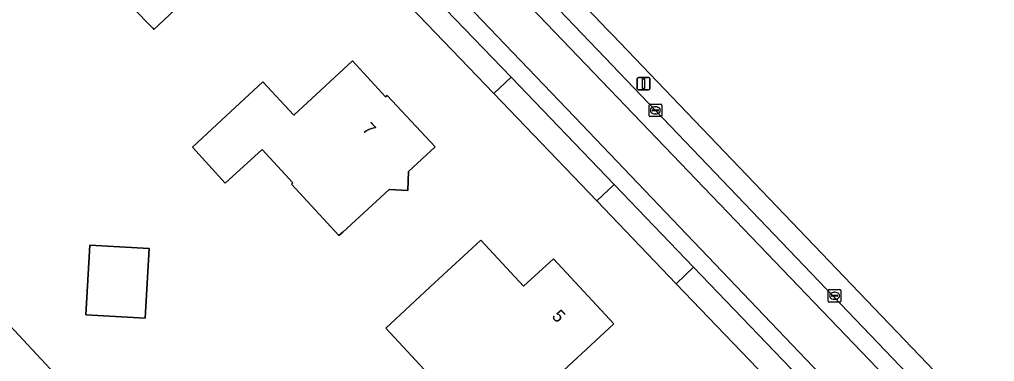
# Model space of a CAD drawing. Extents: x 156702 to 158052, y 387630 to 388992.
# Drawn here: x 157527.1 to 157604.6, y 388126 to 388153.2 of the extents above; entities that cross this region are included whole.
import ezdxf

# ---------------------------------------------------------------- set-up
doc = ezdxf.new("R2010")
doc.units = 0
for name, color, linetype in [('IMGEO_Erf', 7, 'Continuous'), ('IMGEO_Kolk', 7, 'Continuous'), ('IMGEO_Lichtmast', 7, 'Continuous'), ('IMGEO_Pand', 7, 'Continuous'), ('IMGEO_Pand_nummerreeks', 7, 'Continuous'), ('IMGEO_Pand_overbouw', 7, 'Continuous'), ('IMGEO_Rijbaan_lokaal_open', 7, 'Continuous'), ('IMGEO_Voetpad_open', 7, 'Continuous')]:
    doc.layers.add(name, color=color, linetype=linetype)

msp = doc.modelspace()

# ---------------------------------------------------------------- linework, layer by layer
at = {"layer": 'IMGEO_Erf'}
for points in [[(157587.035, 388124.121), (157579.276, 388132.213), (157572.963, 388138.799), (157564.783, 388147.336), (157558.148, 388154.267), (157555.656, 388156.858), (157540.509, 388172.666), (157529.678, 388184.162), (157518.473, 388195.859), (157513.847, 388200.675), (157504.663, 388210.298), (157501.613, 388213.475), (157500.203, 388214.779)], [(157525.186, 388203.161), (157531.652, 388196.446), (157531.904, 388196.084), (157532.708, 388195.257), (157533.058, 388194.995), (157540.381, 388187.324), (157540.603, 388187.003), (157540.852, 388186.863), (157546.974, 388180.453), (157548.872, 388178.469), (157549.792, 388177.507), (157561.008, 388165.78), (157561.677, 388165.081), (157562.03, 388164.713), (157565.006, 388161.615), (157565.368, 388161.238), (157570.562, 388155.83), (157572.789, 388153.497), (157573.82, 388152.417), (157574.214, 388152.004), (157593.208, 388132.152), (157609.438, 388115.184)]]:
    msp.add_lwpolyline(points, dxfattribs=at)
for points in [[(157546.37, 388142.894), (157543.444, 388140.22), (157540.833, 388143.085), (157542.762, 388144.87), (157546.431, 388148.265), (157548.884, 388145.629), (157553.543, 388149.959), (157556.188, 388147.085), (157556.301, 388147.194), (157560.112, 388143.094), (157558.006, 388141.139), (157557.943, 388139.618), (157556.458, 388139.708), (157552.782, 388136.32), (157552.473, 388136.036), (157548.693, 388140.141), (157548.805, 388140.243)], [(157559.128, 388124.602), (157559.582, 388125.024), (157556.195, 388128.667), (157560.077, 388132.277), (157563.738, 388135.681), (157567.141, 388132.006), (157569.518, 388134.192), (157574.323, 388129.024), (157570.657, 388125.625), (157568.76, 388123.866), (157571.405, 388121.014), (157568.776, 388118.575), (157566.131, 388121.427), (157563.948, 388119.403)], [(157532.669, 388135.275), (157537.389, 388135.006), (157537.074, 388129.477), (157532.354, 388129.747)], [(157510.363, 388087.71), (157500, 388098.923), (157496.856, 388102.325), (157500, 388105.237), (157525.959, 388129.281), (157532.764, 388121.951), (157518.177, 388108.448), (157524.906, 388101.181)]]:
    msp.add_lwpolyline(points, close=True, dxfattribs=at)
at = {"layer": 'IMGEO_Kolk'}
for p, q in [((157577.121, 388145.58), (157577.121, 388146.432)), ((157577.196, 388146.506), (157578.048, 388146.506)), ((157577.609, 388146.286), (157577.634, 388146.286)), ((157578.122, 388146.432), (157578.122, 388145.58)), ((157578.048, 388145.506), (157577.196, 388145.506)), ((157577.38, 388146), (157577.38, 388146.012)), ((157577.818, 388145.963), (157577.42, 388145.963)), ((157577.423, 388146.049), (157577.821, 388146.049)), ((157577.632, 388145.726), (157577.607, 388145.726)), ((157577.864, 388146.012), (157577.864, 388146)), ((157591.363, 388130.828), (157591.363, 388131.68)), ((157591.438, 388131.754), (157592.29, 388131.754)), ((157591.851, 388131.534), (157591.876, 388131.534)), ((157592.364, 388131.68), (157592.364, 388130.828)), ((157592.29, 388130.754), (157591.438, 388130.754)), ((157591.622, 388131.248), (157591.622, 388131.26)), ((157592.06, 388131.211), (157591.662, 388131.211)), ((157591.665, 388131.297), (157592.063, 388131.297)), ((157591.874, 388130.974), (157591.849, 388130.974)), ((157592.106, 388131.26), (157592.106, 388131.248))]:
    msp.add_line(p, q, dxfattribs=at)
for points in [[(157577.121, 388145.58), (157577.121, 388146.432)], [(157577.196, 388146.506), (157578.048, 388146.506)], [(157578.122, 388146.432), (157578.122, 388145.58)], [(157578.048, 388145.506), (157577.196, 388145.506)], [(157591.363, 388130.828), (157591.363, 388131.68)], [(157591.438, 388131.754), (157592.29, 388131.754)], [(157592.364, 388131.68), (157592.364, 388130.828)], [(157592.29, 388130.754), (157591.438, 388130.754)]]:
    msp.add_lwpolyline(points, dxfattribs=at)
for centre, radius, start, end in [((157577.198, 388146.43), 0.0765, 91.55205, 178.44795), ((157577.198, 388146.43), 0.0765, 91.55205, 178.44795), ((157578.046, 388146.43), 0.0765, 1.55205, 88.44795), ((157578.046, 388146.43), 0.0765, 1.55205, 88.44795), ((157577.198, 388145.582), 0.0765, 181.55205, 268.44795), ((157577.198, 388145.582), 0.0765, 181.55205, 268.44795), ((157577.42, 388146.009), 0.0403, 85.87752, 175.75265), ((157577.417, 388145.999), 0.0366, 178.93798, 274.71019), ((157577.821, 388146.006), 0.043, 264.86636, 352.45326), ((157577.825, 388146.011), 0.0386, 1.73085, 96.63898), ((157578.046, 388145.582), 0.0765, 271.55205, 358.44795), ((157578.046, 388145.582), 0.0765, 271.55205, 358.44795), ((157591.44, 388131.678), 0.0765, 91.55205, 178.44795), ((157591.44, 388131.678), 0.0765, 91.55205, 178.44795), ((157592.288, 388131.678), 0.0765, 1.55205, 88.44795), ((157592.288, 388131.678), 0.0765, 1.55205, 88.44795), ((157591.44, 388130.83), 0.0765, 181.55205, 268.44795), ((157591.44, 388130.83), 0.0765, 181.55205, 268.44795), ((157591.662, 388131.257), 0.0403, 85.87752, 175.75265), ((157591.659, 388131.247), 0.0366, 178.93798, 274.71019), ((157592.063, 388131.254), 0.043, 264.86636, 352.45326), ((157592.067, 388131.259), 0.0386, 1.73085, 96.63898), ((157592.288, 388130.83), 0.0765, 271.55205, 358.44795), ((157592.288, 388130.83), 0.0765, 271.55205, 358.44795)]:
    msp.add_arc(centre, radius, start, end, dxfattribs=at)
for centre, major_axis, ratio, start_param, end_param in [((157577.608, 388146.006), (-0.387, 0.002), 0.722429, 4.712389, 7.853982), ((157577.633, 388146.006), (-0.39, 0.002), 0.717154, 1.570796, 4.712389), ((157591.85, 388131.254), (-0.387, 0.002), 0.722429, 4.712389, 7.853982), ((157591.875, 388131.254), (-0.39, 0.002), 0.717154, 1.570796, 4.712389)]:
    msp.add_ellipse(centre, major_axis=major_axis, ratio=ratio, start_param=start_param, end_param=end_param, dxfattribs=at)
at = {"layer": 'IMGEO_Lichtmast'}
for p, q in [((157576.187, 388147.729), (157576.187, 388148.529)), ((157576.187, 388148.529), (157576.187, 388147.729)), ((157576.287, 388148.629), (157577.077, 388148.629)), ((157577.077, 388148.629), (157576.287, 388148.629)), ((157577.177, 388148.529), (157577.177, 388147.729)), ((157577.177, 388147.729), (157577.177, 388148.529)), ((157577.077, 388147.629), (157576.287, 388147.629)), ((157576.287, 388147.629), (157577.077, 388147.629))]:
    msp.add_line(p, q, dxfattribs=at)
msp.add_lwpolyline([(157576.607, 388148.504), (157576.757, 388148.504), (157576.757, 388147.754), (157576.607, 388147.754), (157576.607, 388148.504)], dxfattribs=at)
for centre, start, end in [((157576.287, 388148.529), 90, 180), ((157576.287, 388148.529), 90, 180), ((157577.077, 388148.529), 0, 90), ((157577.077, 388148.529), 360, 90), ((157576.287, 388147.729), 180, 270), ((157576.287, 388147.729), 180, 270), ((157577.077, 388147.729), 270, 0), ((157577.077, 388147.729), 270, 0)]:
    msp.add_arc(centre, 0.1, start, end, dxfattribs=at)
at = {"layer": 'IMGEO_Pand'}
for points in [[(157552.473, 388136.036), (157552.782, 388136.32), (157556.458, 388139.708), (157557.943, 388139.618), (157558.006, 388141.139), (157560.112, 388143.094), (157556.301, 388147.194), (157556.188, 388147.085), (157553.543, 388149.959), (157548.884, 388145.629), (157546.431, 388148.265), (157542.762, 388144.87), (157540.833, 388143.085), (157543.444, 388140.22), (157546.37, 388142.894), (157548.805, 388140.243), (157548.693, 388140.141)], [(157574.323, 388129.024), (157569.518, 388134.192), (157567.141, 388132.006), (157563.738, 388135.681), (157560.077, 388132.277), (157556.195, 388128.667), (157559.582, 388125.024), (157559.128, 388124.602), (157563.948, 388119.403), (157566.131, 388121.427), (157568.776, 388118.575), (157571.405, 388121.014), (157568.76, 388123.866), (157570.657, 388125.625)], [(157532.354, 388129.747), (157537.074, 388129.477), (157537.389, 388135.006), (157532.669, 388135.275)], [(157510.363, 388087.71), (157524.906, 388101.181), (157518.177, 388108.448), (157532.764, 388121.951), (157525.959, 388129.281), (157500, 388105.237), (157496.856, 388102.325), (157500, 388098.923)]]:
    msp.add_lwpolyline(points, close=True, dxfattribs=at)
at = {"layer": 'IMGEO_Pand_overbouw'}
msp.add_lwpolyline([(157534.533, 388155.796), (157537.649, 388152.569), (157537.775, 388152.439), (157539.431, 388154.015), (157537.169, 388156.349)], close=True, dxfattribs=at)
at = {"layer": 'IMGEO_Rijbaan_lokaal_open'}
for points in [[(157609.911, 388112.196), (157591.786, 388131.202), (157577.621, 388146.005), (157573.012, 388150.836), (157569.341, 388154.667), (157564.008, 388160.23), (157559.757, 388164.664), (157549.961, 388174.881), (157545.763, 388179.279), (157539.44, 388185.889), (157536.509, 388188.937), (157524.471, 388201.521), (157523.994, 388202.001), (157516.86, 388209.457), (157516.607, 388209.721), (157507.617, 388218.991), (157506.291, 388220.397), (157505.252, 388219.445), (157569.611, 388152.266), (157609.631, 388110.47)], [(157624.063, 388095.085), (157622.801, 388096.503), (157622.266, 388097.074), (157611.799, 388108.253), (157611.22, 388108.439), (157611.207, 388108.452), (157610.633, 388109.036), (157609.788, 388109.895), (157609.631, 388110.47), (157569.611, 388152.266), (157505.252, 388219.445), (157502.666, 388217.076), (157520.881, 388198.047), (157571.193, 388145.504), (157602.434, 388112.73)], [(157520.881, 388198.047), (157502.666, 388217.076), (157501.5, 388216.007), (157502.813, 388214.652), (157503.415, 388215.215), (157506.471, 388212.039), (157505.936, 388211.53), (157515.137, 388201.917), (157519.764, 388197.104), (157530.97, 388185.39), (157541.858, 388174.01), (157557.021, 388158.183), (157559.496, 388155.588), (157566.169, 388148.651), (157574.344, 388140.111), (157580.64, 388133.535), (157588.386, 388125.454), (157602.101, 388110.987), (157604.416, 388109.059)], [(157602.434, 388112.73), (157571.193, 388145.504), (157520.881, 388198.047)]]:
    msp.add_lwpolyline(points, dxfattribs=at)
at = {"layer": 'IMGEO_Voetpad_open'}
for points in [[(157574.214, 388152.004), (157573.82, 388152.417), (157572.789, 388153.497), (157570.562, 388155.83), (157565.368, 388161.238), (157564.437, 388160.383), (157564.295, 388160.496), (157564.008, 388160.23), (157569.341, 388154.667), (157573.012, 388150.836), (157577.621, 388146.005), (157591.786, 388131.202), (157609.911, 388112.196), (157611.15, 388113.418), (157609.438, 388115.184), (157593.208, 388132.152)], [(157559.496, 388155.588), (157558.148, 388154.267), (157564.783, 388147.336), (157566.169, 388148.651)], [(157574.344, 388140.111), (157566.169, 388148.651), (157564.783, 388147.336), (157572.963, 388138.799)], [(157580.64, 388133.535), (157574.344, 388140.111), (157572.963, 388138.799), (157579.276, 388132.213)], [(157588.386, 388125.454), (157580.64, 388133.535), (157579.276, 388132.213), (157587.035, 388124.121)]]:
    msp.add_lwpolyline(points, close=True, dxfattribs=at)

# ---------------------------------------------------------------- texts
at = {"layer": 'IMGEO_Pand_nummerreeks'}
for s, rotation, p in [('7', 313.73777, (157554.267, 388144.458)), ('5', 312.91433, (157569.332, 388129.577))]:
    msp.add_text(s, height=1, rotation=rotation, dxfattribs=at).set_placement(p)

doc.saveas('drawing.dxf')
